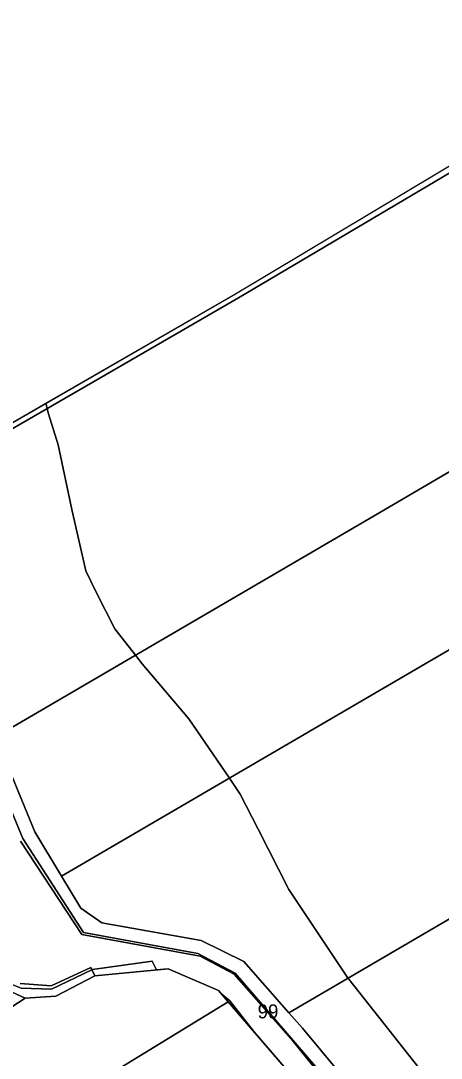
# Model space of a CAD drawing. Extents: x -522079 to -518833, y -1142400 to -1139961.
# Drawn here: x -520688.5 to -520538, y -1140520.9 to -1140149.5 of the extents above; entities that cross this region are included whole.
import ezdxf

# ---------------------------------------------------------------- set-up
doc = ezdxf.new("R2010")
doc.units = 0
for name, color, linetype in [('95560013', 7, 'Continuous'), ('95610013', 7, 'Continuous'), ('95630013', 7, 'Continuous'), ('95640013', 7, 'Continuous'), ('95660013', 7, 'Continuous')]:
    doc.layers.add(name, color=color, linetype=linetype)

msp = doc.modelspace()

# ---------------------------------------------------------------- linework, layer by layer
at = {"layer": '95560013'}
for points in [[(-520697.54, -1140405.82), (-520704.93, -1140387.92), (-520719.64, -1140344.89), (-520729.96, -1140323.84), (-520727.12, -1140316.09), (-520610.57, -1140248.68), (-520489.41, -1140176.97), (-520443.64, -1140149.48), (-520437.53, -1140151.12), (-520407.86, -1140236.34), (-520563.45, -1140327.62)], [(-520407.86, -1140236.34), (-520389.24, -1140289.48), (-520535.21, -1140374.77), (-520673.87, -1140455.8), (-520683.48, -1140439.85), (-520697.54, -1140405.82), (-520563.45, -1140327.62)], [(-520592.52, -1140504.62), (-520608.7, -1140486.32), (-520623.97, -1140478.75), (-520659.41, -1140472.47), (-520666.98, -1140467.24), (-520673.87, -1140455.8), (-520535.21, -1140374.77), (-520389.24, -1140289.48), (-520361.23, -1140369.4)], [(-520361.23, -1140369.4), (-520345.47, -1140414.38), (-520469.06, -1140486.19), (-520562.49, -1140540.48), (-520587.65, -1140510.13), (-520592.52, -1140504.62)]]:
    msp.add_lwpolyline(points, close=True, dxfattribs=at)
at = {"layer": '95610013'}
for points in [[(-520732.54, -1140476.21), (-520724, -1140470.78), (-520714.97, -1140487.48), (-520699.14, -1140493.81), (-520686.89, -1140499.45), (-520708.82, -1140513.67)], [(-520686.89, -1140499.45), (-520675.92, -1140498.77), (-520661.91, -1140491.42), (-520635.69, -1140488.94), (-520617.72, -1140496.63), (-520614.24, -1140500.69), (-520688.32, -1140546.05), (-520708.82, -1140513.67)], [(-520688.32, -1140546.05), (-520614.24, -1140500.69), (-520587.68, -1140531.64), (-520567.56, -1140556.74), (-520562.84, -1140560.36), (-520646.64, -1140611.87)]]:
    msp.add_lwpolyline(points, close=True, dxfattribs=at)
at = {"layer": '95630013'}
for points in [[(-520709.46, -1140390.03), (-520687.78, -1140442.24), (-520666, -1140475.86), (-520625.05, -1140483.49), (-520611.7, -1140490.5), (-520560.63, -1140549.81)], [(-520688.63, -1140494.17), (-520677.55, -1140494.96), (-520663.43, -1140488.4), (-520661.91, -1140491.42), (-520675.92, -1140498.77), (-520686.89, -1140499.45), (-520699.14, -1140493.81)], [(-520587.68, -1140531.64), (-520614.24, -1140500.69), (-520617.72, -1140496.63), (-520635.69, -1140488.94), (-520661.91, -1140491.42), (-520663.43, -1140488.4), (-520677.55, -1140494.96), (-520688.63, -1140494.17)]]:
    msp.add_lwpolyline(points, dxfattribs=at)
at = {"layer": '95640013'}
for points in [[(-520489.41, -1140176.97), (-520610.57, -1140248.68), (-520727.12, -1140316.09), (-520736.79, -1140321.94), (-520738.8, -1140318.04), (-520737.2, -1140317.47), (-520736.37, -1140319.22), (-520728.21, -1140314.51), (-520611.62, -1140247.2), (-520491.09, -1140175.17)], [(-520560.63, -1140549.81), (-520611.7, -1140490.5), (-520625.05, -1140483.49), (-520666, -1140475.86), (-520687.78, -1140442.24), (-520709.46, -1140390.03), (-520724.04, -1140346.68), (-520736.79, -1140321.94), (-520727.12, -1140316.09), (-520729.96, -1140323.84), (-520719.64, -1140344.89), (-520704.93, -1140387.92), (-520697.54, -1140405.82), (-520683.48, -1140439.85), (-520673.87, -1140455.8), (-520666.98, -1140467.24), (-520659.41, -1140472.47), (-520623.97, -1140478.75), (-520608.7, -1140486.32), (-520592.52, -1140504.62), (-520587.65, -1140510.13), (-520562.49, -1140540.48)]]:
    msp.add_lwpolyline(points, dxfattribs=at)
at = {"layer": '95660013'}
for points in [[(-520542.49, -1140528.86), (-520571.02, -1140492.64), (-520571.34, -1140492.23), (-520571.5, -1140492.02), (-520592.55, -1140460.53), (-520603.54, -1140438.95), (-520609.92, -1140426.44), (-520613.83, -1140420.71), (-520628.38, -1140399.39), (-520645.01, -1140379.75), (-520647.47, -1140376.62), (-520654.86, -1140367.24), (-520661.31, -1140354.3), (-520663.36, -1140350.18), (-520665.2, -1140346.48), (-520670.25, -1140324.52), (-520675.06, -1140301.35), (-520678.51, -1140290.17), (-520678.74, -1140289.42), (-520679.03, -1140288.27), (-520679.51, -1140286.39), (-520611.62, -1140247.2), (-520491.09, -1140175.17)], [(-520728.21, -1140314.51), (-520679.51, -1140286.39), (-520679.03, -1140288.27), (-520678.74, -1140289.42), (-520678.51, -1140290.17), (-520675.06, -1140301.35), (-520670.25, -1140324.52), (-520665.2, -1140346.48), (-520663.36, -1140350.18), (-520661.31, -1140354.3), (-520654.86, -1140367.24), (-520647.47, -1140376.62), (-520645.01, -1140379.75), (-520628.38, -1140399.39), (-520613.83, -1140420.71), (-520609.92, -1140426.44), (-520603.54, -1140438.95), (-520592.55, -1140460.53), (-520571.5, -1140492.02), (-520571.34, -1140492.23), (-520571.02, -1140492.64), (-520542.49, -1140528.86)], [(-520688.6, -1140443.21), (-520666.58, -1140476.66), (-520624.22, -1140484.36), (-520612.12, -1140490.78), (-520591.73, -1140514.02), (-520562.29, -1140550.47)], [(-520562.29, -1140550.47), (-520591.73, -1140514.02), (-520612.12, -1140490.78), (-520624.22, -1140484.36), (-520666.58, -1140476.66), (-520688.6, -1140443.21)], [(-520587.68, -1140531.64), (-520605.08, -1140511.36), (-520613.7, -1140500.4), (-520616.5, -1140498.05), (-520617.72, -1140496.63), (-520635.69, -1140488.94), (-520639.91, -1140489.34), (-520641.39, -1140486.23), (-520662.78, -1140489.2), (-520662.98, -1140489.3), (-520677.52, -1140496.19), (-520688.28, -1140495.8), (-520706.32, -1140488.67)], [(-520706.32, -1140488.67), (-520688.28, -1140495.8), (-520677.52, -1140496.19), (-520662.98, -1140489.3), (-520662.78, -1140489.2), (-520641.39, -1140486.23), (-520639.91, -1140489.34), (-520635.69, -1140488.94), (-520617.72, -1140496.63), (-520616.5, -1140498.05), (-520613.7, -1140500.4), (-520605.08, -1140511.36), (-520587.68, -1140531.64)]]:
    msp.add_lwpolyline(points, dxfattribs=at)

# ---------------------------------------------------------------- texts
msp.add_text('99', height=5, rotation=360, dxfattribs=at).set_placement((-520603.71, -1140506.66))

doc.saveas('drawing.dxf')
